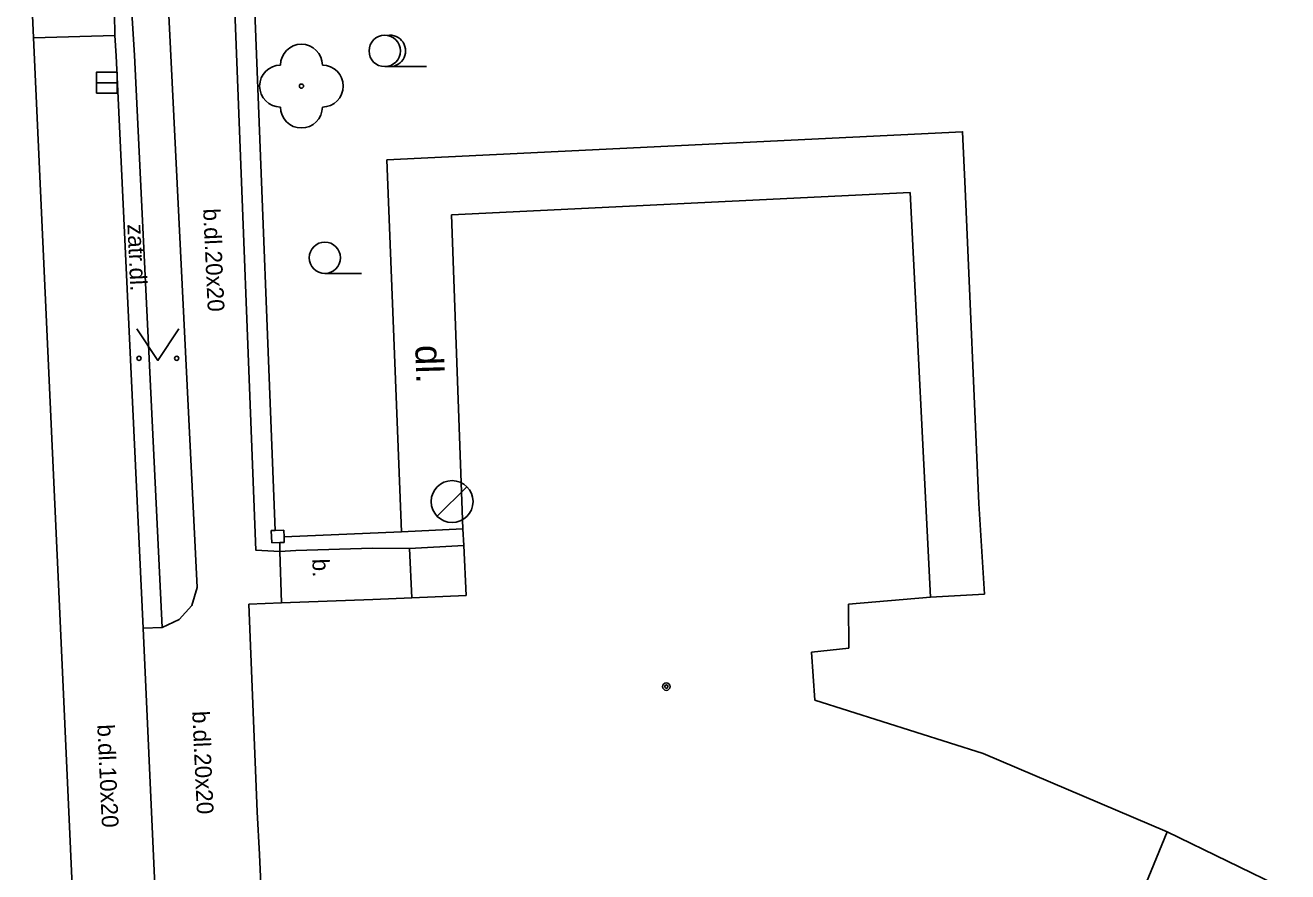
# Model space of a CAD drawing. Extents: x -600309 to -598967, y -1161267 to -1160292.
# Drawn here: x -599770.21 to -599740.04, y -1160541.07 to -1160520.86 of the extents above; entities that cross this region are included whole.
import ezdxf

# ---------------------------------------------------------------- set-up
doc = ezdxf.new("R2010")
doc.units = 0
for name, color, linetype in [('Level 10', 7, 'Continuous'), ('Level 11', 7, 'Continuous'), ('Level 22', 7, 'Continuous'), ('Level 27', 7, 'Continuous'), ('Level 36', 7, 'Continuous'), ('Level 39', 7, 'Continuous'), ('Level 40', 7, 'Continuous'), ('Level 5', 7, 'Continuous'), ('Level 51', 7, 'Continuous'), ('Level 7', 7, 'Continuous'), ('Level 8', 7, 'Continuous')]:
    doc.layers.add(name, color=color, linetype=linetype)

msp = doc.modelspace()

# ---------------------------------------------------------------- linework, layer by layer
at = {"layer": 'Level 10'}
for points in [[(-599768.07, -1160521.1), (-599768.08, -1160520.58), (-599768.24, -1160517.09), (-599768.26, -1160516.63)], [(-599766.65, -1160551.9), (-599766.98, -1160544.38), (-599767.39, -1160535.25), (-599768.04, -1160521.59), (-599768.07, -1160521.1)]]:
    msp.add_lwpolyline(points, dxfattribs=at)
at = {"layer": 'Level 11'}
for points in [[(-599770.01, -1160521.16), (-599770.21, -1160516.72)], [(-599767.66, -1160520.56), (-599767.6, -1160521.57), (-599766.94, -1160535.24)], [(-599766.1, -1160534.28), (-599766.78, -1160520.62), (-599766.78, -1160520.52)], [(-599770.01, -1160521.16), (-599768.07, -1160521.1)], [(-599768.61, -1160551.94), (-599769.39, -1160534.73), (-599770.01, -1160521.16)], [(-599747.42, -1160532.28), (-599747.29, -1160534.44), (-599748.58, -1160534.51)], [(-599761.03, -1160533.35), (-599760.97, -1160534.53)], [(-599764.09, -1160534.65), (-599764.13, -1160533.42)], [(-599766.23, -1160534.71), (-599766.1, -1160534.28)], [(-599766.23, -1160534.71), (-599766.53, -1160535.05), (-599766.94, -1160535.24)], [(-599766.94, -1160535.24), (-599767.39, -1160535.25)]]:
    msp.add_lwpolyline(points, dxfattribs=at)
at = {"layer": 'Level 22'}
msp.add_circle((-599763.61, -1160522.31), 0.05, dxfattribs=at)
for centre, start, end in [((-599763.61, -1160521.81), 0, 180), ((-599764.11, -1160522.31), 90, 270), ((-599763.11, -1160522.31), 270, 90), ((-599763.61, -1160522.81), 180, 0)]:
    msp.add_arc(centre, 0.5, start, end, dxfattribs=at)
at = {"layer": 'Level 27'}
for p, q in [((-599768.51, -1160522.23), (-599768.01, -1160522.23)), ((-599760.364, -1160532.583), (-599759.657, -1160531.876))]:
    msp.add_line(p, q, dxfattribs=at)
msp.add_lwpolyline([(-599768.51, -1160522.48), (-599768.01, -1160522.48), (-599768.01, -1160521.98), (-599768.51, -1160521.98)], close=True, dxfattribs=at)
msp.add_circle((-599760.01, -1160532.23), 0.5, dxfattribs=at)
at = {"layer": 'Level 36'}
for p, q in [((-599761.62, -1160521.845), (-599760.62, -1160521.845)), ((-599763.05, -1160526.7849), (-599762.175, -1160526.7849))]:
    msp.add_line(p, q, dxfattribs=at)
msp.add_lwpolyline([(-599767.54, -1160528.11), (-599767.04, -1160528.86), (-599766.54, -1160528.11)], dxfattribs=at)
for centre, radius in [((-599761.62, -1160521.4696), 0.375), ((-599763.0501, -1160526.4098), 0.375), ((-599767.4902, -1160528.8098), 0.05), ((-599766.5908, -1160528.8098), 0.05)]:
    msp.add_circle(centre, radius, dxfattribs=at)
msp.add_arc((-599761.495, -1160521.4696), 0.375, 260.40593, 99.59407, dxfattribs=at)
at = {"layer": 'Level 39'}
for radius in [0.09, 0.0398]:
    msp.add_circle((-599754.89, -1160536.65), radius, dxfattribs=at)
at = {"layer": 'Level 5'}
for points in [[(-599760.02, -1160525.38), (-599749.06, -1160524.85)], [(-599749.06, -1160524.85), (-599748.58, -1160534.51)], [(-599759.75, -1160532.88), (-599760.02, -1160525.38)], [(-599764.33, -1160532.92), (-599764.24, -1160532.92), (-599764.03, -1160532.91)], [(-599764.32, -1160533.22), (-599764.33, -1160532.92)], [(-599764.03, -1160532.91), (-599764.02, -1160533.07), (-599764.02, -1160533.21)], [(-599759.73, -1160533.28), (-599759.75, -1160532.88)], [(-599764.13, -1160533.21), (-599764.32, -1160533.22)], [(-599764.02, -1160533.21), (-599764.13, -1160533.21)], [(-599759.67, -1160534.47), (-599759.73, -1160533.28)], [(-599759.67, -1160534.47), (-599760.97, -1160534.53), (-599761.9, -1160534.57), (-599764.09, -1160534.65), (-599764.87, -1160534.68)], [(-599748.58, -1160534.51), (-599750.54, -1160534.68)], [(-599764.87, -1160534.68), (-599764.67, -1160539.64)], [(-599750.54, -1160534.68), (-599750.53, -1160535.73)], [(-599750.53, -1160535.73), (-599751.42, -1160535.83)], [(-599751.42, -1160535.83), (-599751.34, -1160536.9699)], [(-599751.34, -1160536.9699), (-599747.32, -1160538.25)], [(-599747.32, -1160538.25), (-599742.92, -1160540.12)], [(-599742.92, -1160540.12), (-599747.15, -1160550.42)], [(-599742.92, -1160540.12), (-599740.04, -1160541.52)], [(-599764.61, -1160540.66), (-599764.41, -1160545.07)]]:
    msp.add_lwpolyline(points, dxfattribs=at)
at = {"layer": 'Level 51'}
for points in [[(-599761.57, -1160524.07), (-599747.81, -1160523.4), (-599747.75, -1160524.76), (-599747.42, -1160532.28)], [(-599761.2199, -1160532.95), (-599761.57, -1160524.07)]]:
    msp.add_lwpolyline(points, dxfattribs=at)
at = {"layer": 'Level 7'}
for points in [[(-599764.13, -1160533.42), (-599764.7, -1160533.39), (-599765.2, -1160520.51), (-599765.2, -1160520.41)], [(-599764.73, -1160520.29), (-599764.72, -1160520.54), (-599764.24, -1160532.92)], [(-599761.2199, -1160532.95), (-599764.02, -1160533.07)], [(-599759.75, -1160532.88), (-599761.2199, -1160532.95)], [(-599764.13, -1160533.42), (-599764.13, -1160533.21)], [(-599764.13, -1160533.42), (-599763.74, -1160533.4), (-599761.9099, -1160533.34)], [(-599761.9099, -1160533.34), (-599761.03, -1160533.35)], [(-599761.03, -1160533.35), (-599759.73, -1160533.28)]]:
    msp.add_lwpolyline(points, dxfattribs=at)
at = {"layer": 'Level 8'}
msp.add_lwpolyline([(-599764.67, -1160539.64), (-599764.61, -1160540.66)], dxfattribs=at)

# ---------------------------------------------------------------- texts
at = {"layer": 'Level 40'}
for s, height, rotation, p in [('b.dl.20x20', 0.4, 272.66055, (-599765.96, -1160525.24)), ('zatr.dl.', 0.4, 272.66055, (-599767.77, -1160525.61)), ('dl.', 0.65, 271.68019, (-599760.89, -1160528.5)), ('b.', 0.4, 271.89682, (-599763.35, -1160533.6)), ('b.dl.20x20', 0.4, 272.66055, (-599766.22, -1160537.24)), ('b.dl.10x20', 0.4, 272.66055, (-599768.49, -1160537.56))]:
    msp.add_text(s, height=height, rotation=rotation, dxfattribs=at).set_placement(p)

doc.saveas('drawing.dxf')
